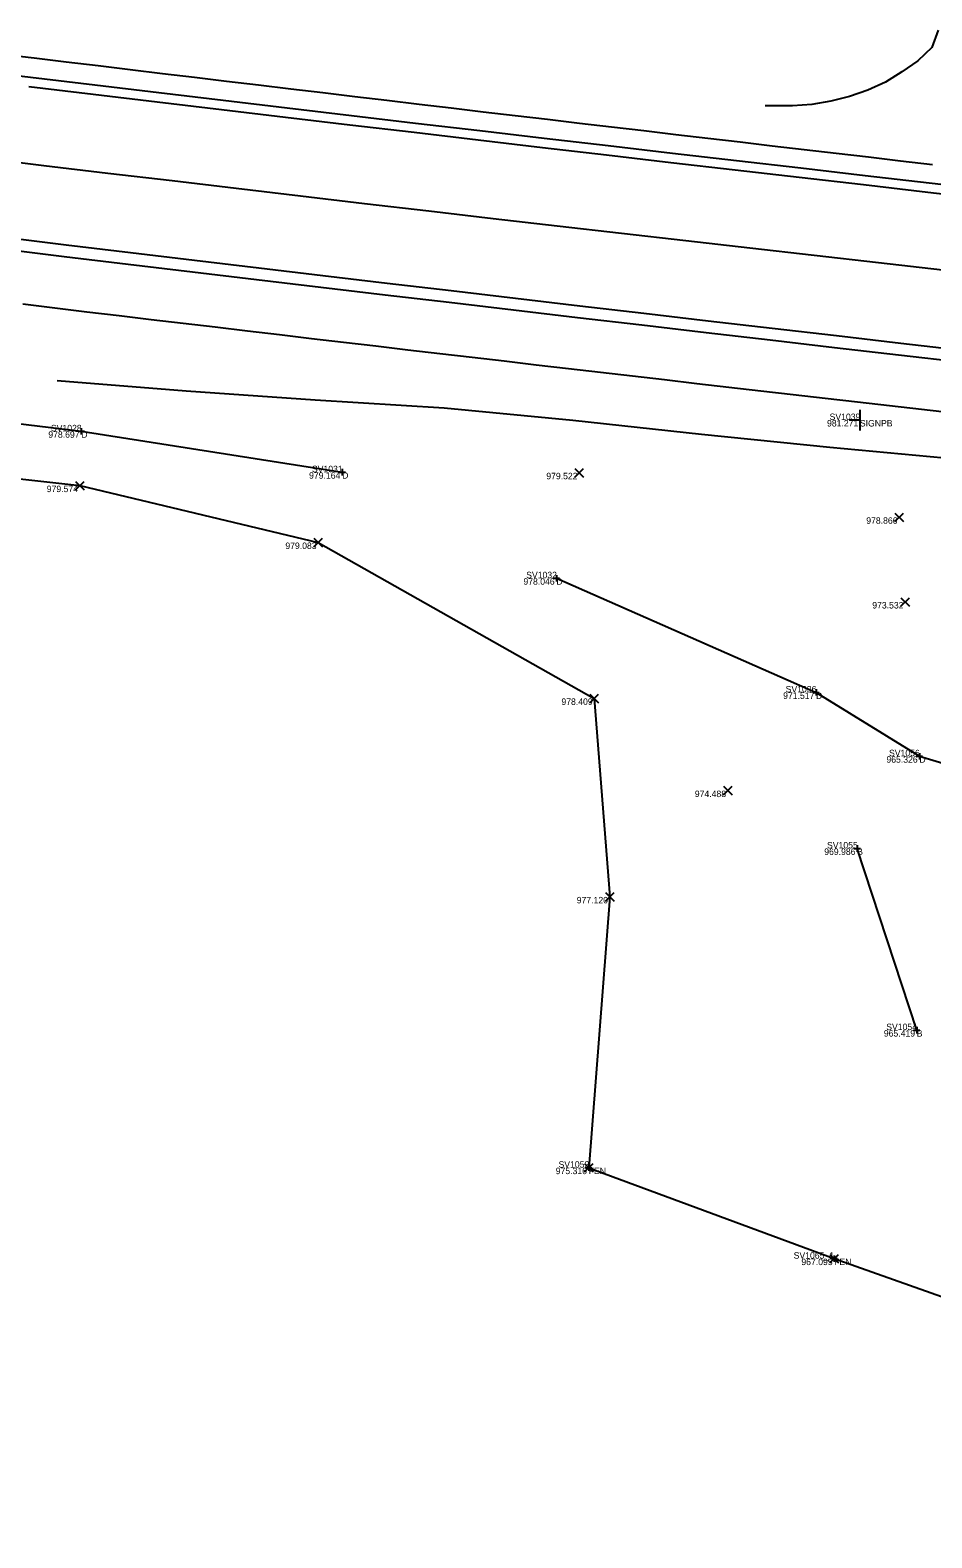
# Model space of a CAD drawing. Extents: x 2065431 to 2068157, y 709104 to 709719.
# Drawn here: x 2066978 to 2067117.5, y 709135.4 to 709368.8 of the extents above; entities that cross this region are included whole.
import ezdxf

# ---------------------------------------------------------------- set-up
doc = ezdxf.new("R2010")
doc.units = 0
for name, color, linetype in [('DT_X_Break_Line', 7, 'Continuous'), ('DT_X_Terrain_Boundary', 7, 'Continuous'), ('PM_X_Edge_Line', 7, 'Continuous'), ('PM_X_Lane_Line', 7, 'Continuous'), ('PV_X_EOP', 7, 'Continuous'), ('PV_X_Shoulder_Rumble_Strip', 7, 'Continuous'), ('RD_X_Fence', 7, 'Continuous'), ('RS_Raster1', 7, 'Continuous'), ('RW_X_CL_100_Bearings', 7, 'Continuous'), ('RW_X_CL_100_Cardinal_Points', 7, 'Continuous'), ('RW_X_Fee_WL', 7, 'Continuous'), ('SV_X_Break_Lines', 7, 'Continuous'), ('SV_X_Mon_Cells_Found', 7, 'Continuous'), ('SV_X_Text_Elevation', 7, 'Continuous'), ('SV_X_Text_Name', 7, 'Continuous')]:
    doc.layers.add(name, color=color, linetype=linetype)

msp = doc.modelspace()

# ---------------------------------------------------------------- linework, layer by layer
at = {"layer": 'DT_X_Break_Line'}
msp.add_lwpolyline([(2066982.19, 709314.51), (2067002.13, 709312.93), (2067022.08, 709311.53), (2067042.04, 709310.28), (2067061.95, 709308.39), (2067081.83, 709306.24), (2067101.73, 709304.2), (2067121.64, 709302.33)], dxfattribs=at)
at = {"layer": 'DT_X_Terrain_Boundary'}
msp.add_lwpolyline([(2066852.77, 709341.57), (2066857.73, 709340.95), (2066862.69, 709340.33), (2066867.65, 709339.72), (2066872.62, 709339.1), (2066877.58, 709338.48), (2066882.54, 709337.87), (2066887.5, 709337.25), (2066908.73, 709315.06), (2066908.28, 709308.83), (2066944.81, 709302.84), (2066985.68, 709298.25), (2067022.53, 709289.45), (2067065.26, 709265.32), (2067067.67, 709234.6), (2067064.4, 709192.69), (2067102.37, 709178.61), (2067140.67, 709165.08)], dxfattribs=at)
at = {"layer": 'PM_X_Edge_Line'}
for points in [[(2066977.8, 709360.04), (2066987.73, 709358.85), (2066997.66, 709357.66), (2067007.59, 709356.47), (2067017.52, 709355.29), (2067027.45, 709354.11), (2067037.38, 709352.94), (2067047.31, 709351.77), (2067057.24, 709350.61), (2067067.17, 709349.44), (2067077.11, 709348.29), (2067087.04, 709347.13), (2067096.97, 709345.98), (2067106.91, 709344.84), (2067116.84, 709343.69), (2067126.78, 709342.56)], [(2066973.64, 709336.75), (2066983.57, 709335.55), (2066993.49, 709334.35), (2067003.42, 709333.16), (2067013.35, 709331.97), (2067023.28, 709330.79), (2067033.21, 709329.61), (2067043.14, 709328.44), (2067053.07, 709327.27), (2067063.01, 709326.1), (2067072.94, 709324.93), (2067082.87, 709323.78), (2067092.8, 709322.62), (2067102.74, 709321.47), (2067112.67, 709320.32), (2067122.61, 709319.18)]]:
    msp.add_lwpolyline(points, dxfattribs=at)
at = {"layer": 'PM_X_Lane_Line'}
msp.add_lwpolyline([(2066970.16, 709349.03), (2066980.09, 709347.83), (2066990.02, 709346.64), (2066999.95, 709345.46), (2067009.88, 709344.28), (2067019.81, 709343.1), (2067029.74, 709341.93), (2067039.67, 709340.77), (2067049.61, 709339.61), (2067059.54, 709338.46), (2067069.47, 709337.32), (2067079.41, 709336.18), (2067089.34, 709335.04), (2067099.28, 709333.91), (2067109.22, 709332.79), (2067119.15, 709331.67)], dxfattribs=at)
at = {"layer": 'PV_X_EOP'}
for points in [[(2067118.45, 709368.75), (2067117.47, 709366.07), (2067115.31, 709364.02), (2067112.86, 709362.3), (2067110.32, 709360.7), (2067107.6, 709359.48), (2067104.77, 709358.47), (2067101.86, 709357.78), (2067098.91, 709357.25), (2067095.93, 709357.05), (2067092.93, 709357.05), (2067091.69, 709357.05)], [(2066973.62, 709365.06), (2066978.59, 709364.46), (2066983.55, 709363.86), (2066988.51, 709363.26), (2066993.48, 709362.66), (2066998.44, 709362.06), (2067003.41, 709361.47), (2067008.37, 709360.87), (2067013.34, 709360.27), (2067018.3, 709359.68), (2067023.26, 709359.09), (2067028.23, 709358.49), (2067033.19, 709357.9), (2067038.16, 709357.31), (2067043.12, 709356.72), (2067048.09, 709356.13), (2067053.05, 709355.54), (2067058.02, 709354.96), (2067062.99, 709354.37), (2067067.95, 709353.78), (2067072.92, 709353.2), (2067077.88, 709352.61), (2067082.85, 709352.03), (2067087.81, 709351.45), (2067092.78, 709350.87), (2067097.75, 709350.29), (2067102.71, 709349.71), (2067107.68, 709349.13), (2067112.65, 709348.55), (2067117.61, 709347.97)], [(2066976.84, 709326.37), (2066981.81, 709325.77), (2066986.77, 709325.18), (2066991.74, 709324.59), (2066996.7, 709323.99), (2067001.67, 709323.4), (2067006.63, 709322.81), (2067011.6, 709322.22), (2067016.56, 709321.64), (2067021.53, 709321.05), (2067026.49, 709320.46), (2067031.46, 709319.88), (2067036.42, 709319.29), (2067041.39, 709318.71), (2067046.35, 709318.13), (2067051.32, 709317.55), (2067056.29, 709316.97), (2067061.25, 709316.39), (2067066.22, 709315.81), (2067071.19, 709315.23), (2067076.15, 709314.66), (2067081.12, 709314.08), (2067086.09, 709313.51), (2067091.05, 709312.93), (2067096.02, 709312.36), (2067100.99, 709311.79), (2067105.96, 709311.22), (2067110.92, 709310.65), (2067115.89, 709310.08), (2067120.86, 709309.51)]]:
    msp.add_lwpolyline(points, dxfattribs=at)
at = {"layer": 'PV_X_Shoulder_Rumble_Strip'}
for points in [[(2066968.12, 709362.68), (2066978.05, 709361.48), (2066987.98, 709360.29), (2066997.91, 709359.1), (2067007.84, 709357.91), (2067017.77, 709356.73), (2067027.7, 709355.55), (2067037.63, 709354.38), (2067047.56, 709353.21), (2067057.49, 709352.04), (2067067.43, 709350.88), (2067077.36, 709349.72), (2067087.29, 709348.57), (2067097.23, 709347.42), (2067107.16, 709346.27), (2067117.09, 709345.12), (2067127.03, 709343.99)], [(2066973.32, 709334.94), (2066983.24, 709333.74), (2066993.17, 709332.54), (2067003.1, 709331.35), (2067013.03, 709330.17), (2067022.96, 709328.98), (2067032.89, 709327.8), (2067042.82, 709326.63), (2067052.75, 709325.46), (2067062.68, 709324.29), (2067072.62, 709323.13), (2067082.55, 709321.97), (2067092.48, 709320.81), (2067102.41, 709319.66), (2067112.35, 709318.51), (2067122.28, 709317.37)]]:
    msp.add_lwpolyline(points, dxfattribs=at)
at = {"layer": 'RD_X_Fence'}
msp.add_lwpolyline([(2067064.4, 709192.69), (2067102.37, 709178.61), (2067140.67, 709165.08), (2067183.02, 709149.8), (2067226.35, 709135.4)], dxfattribs=at)
at = {"layer": 'RS_Raster1'}
for p, q in [((2066985.4, 709306.66), (2066986.4, 709306.66)), ((2066985.9, 709307.16), (2066985.9, 709306.16)), ((2066985.9, 709306.66), (2066985.9, 709306.66)), ((2067025.76, 709300.33), (2067026.76, 709300.33)), ((2067026.26, 709300.83), (2067026.26, 709299.83)), ((2067026.26, 709300.33), (2067026.26, 709300.33)), ((2067058.9, 709283.92), (2067059.9, 709283.92)), ((2067059.4, 709284.42), (2067059.4, 709283.42)), ((2067059.4, 709283.92), (2067059.4, 709283.92)), ((2067099.07, 709266.25), (2067100.07, 709266.25)), ((2067099.57, 709266.75), (2067099.57, 709265.75)), ((2067099.57, 709266.25), (2067099.57, 709266.25)), ((2067115.56, 709256.87), (2067115.56, 709255.87)), ((2067115.06, 709256.37), (2067116.06, 709256.37)), ((2067115.56, 709256.37), (2067115.56, 709256.37)), ((2067105.44, 709242.1), (2067106.44, 709242.1)), ((2067105.94, 709242.6), (2067105.94, 709241.6)), ((2067105.94, 709242.1), (2067105.94, 709242.1)), ((2067114.65, 709213.98), (2067115.65, 709213.98)), ((2067115.15, 709214.48), (2067115.15, 709213.48)), ((2067115.15, 709213.98), (2067115.15, 709213.98)), ((2067063.9, 709192.69), (2067064.9, 709192.69)), ((2067064.4, 709193.19), (2067064.4, 709192.19)), ((2067064.4, 709192.69), (2067064.4, 709192.69)), ((2067101.87, 709178.61), (2067102.87, 709178.61)), ((2067102.37, 709179.11), (2067102.37, 709178.11)), ((2067102.37, 709178.61), (2067102.37, 709178.61))]:
    msp.add_line(p, q, dxfattribs=at)
at = {"layer": 'RW_X_CL_100_Bearings'}
for p, q in [((2066985.01, 709297.58), (2066986.35, 709298.92)), ((2066985.01, 709298.92), (2066986.35, 709297.58)), ((2067062.25, 709299.58), (2067063.58, 709300.91)), ((2067062.25, 709300.91), (2067063.58, 709299.58)), ((2067111.77, 709292.68), (2067113.11, 709294.01)), ((2067111.77, 709294.01), (2067113.11, 709292.68)), ((2067021.87, 709288.78), (2067023.2, 709290.12)), ((2067021.87, 709290.12), (2067023.2, 709288.78)), ((2067112.67, 709279.58), (2067114.01, 709280.91)), ((2067112.67, 709280.91), (2067114.01, 709279.58)), ((2067064.6, 709264.66), (2067065.93, 709265.99)), ((2067064.6, 709265.99), (2067065.93, 709264.66)), ((2067085.26, 709250.38), (2067086.59, 709251.72)), ((2067085.26, 709251.72), (2067086.59, 709250.38)), ((2067067, 709233.93), (2067068.33, 709235.26)), ((2067067, 709235.26), (2067068.33, 709233.93)), ((2067063.74, 709192.03), (2067065.07, 709193.36)), ((2067063.74, 709193.36), (2067065.07, 709192.03)), ((2067101.7, 709177.94), (2067103.03, 709179.27)), ((2067101.7, 709179.27), (2067103.03, 709177.94))]:
    msp.add_line(p, q, dxfattribs=at)
at = {"layer": 'RW_X_CL_100_Cardinal_Points'}
for p, q in [((2067106.35, 709308.41), (2067104.75, 709308.41)), ((2067106.35, 709310.01), (2067106.35, 709306.81))]:
    msp.add_line(p, q, dxfattribs=at)
at = {"layer": 'RW_X_Fee_WL'}
for points in [[(2066908.73, 709315.08), (2066947.5, 709311.32), (2066985.9, 709306.66), (2067026.26, 709300.33)], [(2067059.4, 709283.92), (2067099.57, 709266.25), (2067115.56, 709256.37), (2067127.09, 709252.91)]]:
    msp.add_lwpolyline(points, dxfattribs=at)
at = {"layer": 'SV_X_Break_Lines'}
msp.add_lwpolyline([(2067115.15, 709213.98), (2067105.94, 709242.1)], dxfattribs=at)

# ---------------------------------------------------------------- texts
at = {"layer": 'SV_X_Mon_Cells_Found'}
for s, p in [('SV1039', (2067101.67, 709308.41)), ('SV1028', (2066981.2, 709306.66)), ('SV1031', (2067021.58, 709300.33)), ('SV1032', (2067054.73, 709283.92)), ('SV1036', (2067094.87, 709266.25)), ('SV1056', (2067110.86, 709256.37)), ('SV1055', (2067101.27, 709242.1)), ('SV1054', (2067110.43, 709213.98)), ('SV1052', (2067059.73, 709192.69)), ('SV1065_1', (2067096.11, 709178.61))]:
    msp.add_text(s, height=1, dxfattribs=at).set_placement(p)
at = {"layer": 'SV_X_Text_Elevation'}
for s, p in [('SIGNPB', (2067106.35, 709307.41)), ('D', (2066985.9, 709305.66)), ('D', (2067026.26, 709299.33)), ('D', (2067059.4, 709282.92)), ('D', (2067099.57, 709265.25)), ('D', (2067115.56, 709255.37)), ('B', (2067105.94, 709241.1)), ('B', (2067115.15, 709212.98)), ('FEN', (2067064.4, 709191.69)), ('FEN', (2067102.37, 709177.61))]:
    msp.add_text(s, height=1, dxfattribs=at).set_placement(p)
at = {"layer": 'SV_X_Text_Name'}
for s, p in [('981.271', (2067101.27, 709307.41)), ('978.697', (2066980.8, 709305.66)), ('979.164', (2067021.14, 709299.33)), ('979.522', (2067057.84, 709299.24)), ('979.574', (2066980.56, 709297.25)), ('978.866', (2067107.34, 709292.35)), ('979.083', (2067017.47, 709288.45)), ('978.046', (2067054.3, 709282.92)), ('973.532', (2067108.27, 709279.24)), ('971.517', (2067094.48, 709265.25)), ('978.409', (2067060.18, 709264.32)), ('965.326', (2067110.46, 709255.37)), ('974.488', (2067080.82, 709250.05)), ('969.986', (2067100.84, 709241.1)), ('977.120', (2067062.55, 709233.6)), ('965.419', (2067110.06, 709212.98)), ('975.316', (2067059.3, 709191.69)), ('975.316', (2067059.3, 709191.69)), ('967.095', (2067097.3, 709177.61)), ('967.095', (2067097.3, 709177.61))]:
    msp.add_text(s, height=1, dxfattribs=at).set_placement(p)

doc.saveas('drawing.dxf')
